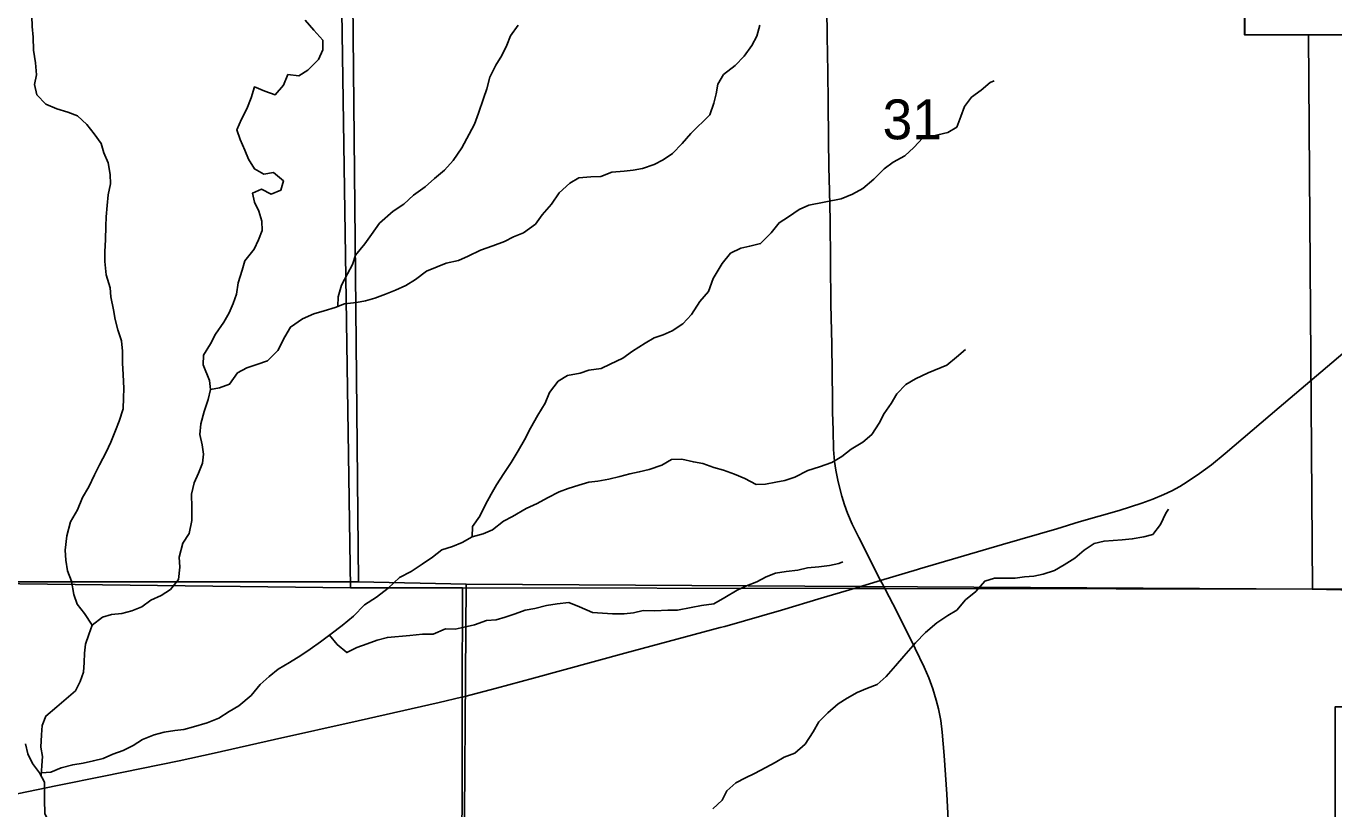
# Model space of a CAD drawing. Extents: x 0 to 34, y 0 to 22.
# Drawn here: x 2.753 to 4.127, y 16.64 to 17.462 of the extents above; entities that cross this region are included whole.
import ezdxf

# ---------------------------------------------------------------- set-up
doc = ezdxf.new("R2010")
doc.units = 0
for name, color, linetype in [('Default', 7, 'Continuous'), ('GM_X_Interstate_Route', 7, 'Continuous'), ('GM_X_Minor_River', 7, 'Continuous'), ('GM_X_Section', 7, 'Continuous'), ('GM_X_Section_Text', 7, 'Continuous'), ('GM_X_State_Route', 7, 'Continuous'), ('GM_X_US_Route', 7, 'Continuous'), ('SH_Text', 7, 'Continuous')]:
    doc.layers.add(name, color=color, linetype=linetype)

msp = doc.modelspace()

# ---------------------------------------------------------------- linework, layer by layer
at = {"layer": 'Default'}
for points in [[(4.0336, 17.4527), (4.0336, 18.2003), (4.0332, 18.2003), (4.0332, 17.4527)], [(4.0336, 18.2003), (5.9872, 18.2003), (5.9872, 17.4527), (4.0336, 17.4527)], [(2.1, 17.8727), (2.1, 16.8795), (2.253, 16.8782), (3.1023, 16.8785), (3.0924, 17.8824)]]:
    msp.add_lwpolyline(points, close=True, dxfattribs=at)
at = {"layer": 'GM_X_Interstate_Route'}
for points in [[(3.0331, 20.9), (2.1, 20.9), (2.1, 16.8784), (2.6014, 16.878), (3.0939, 16.8719), (3.0724, 18.2926), (3.0747, 18.8969), (3.067, 19.3838), (3.0588, 19.9042)], [(2.1, 16.8784), (2.1, 14.1), (3.2011, 14.1), (3.2037, 14.7782), (3.2041, 14.9016), (3.2042, 14.9221), (3.2098, 15.7617), (3.2111, 16.7578), (3.2115, 16.8719), (3.0939, 16.8719), (2.6014, 16.878)]]:
    msp.add_lwpolyline(points, close=True, dxfattribs=at)
for points in [[(3.0724, 18.2926), (3.0939, 16.8719), (3.2115, 16.8719), (3.6203, 16.8714), (3.6554, 16.8713), (4.6269, 16.8701)], [(4.6269, 16.8701), (3.6554, 16.8713), (3.6203, 16.8714), (3.2115, 16.8719), (3.2111, 16.7578), (3.2098, 15.7617), (3.2042, 14.9221), (3.2041, 14.9016), (3.2037, 14.7782), (3.2011, 14.1), (8.2568, 14.1)]]:
    msp.add_lwpolyline(points, dxfattribs=at)
at = {"layer": 'GM_X_Minor_River'}
for points in [[(2.8223, 16.8328), (2.8144, 16.8451), (2.8066, 16.855), (2.8032, 16.8649), (2.8007, 16.879), (2.7966, 16.89), (2.7948, 16.901), (2.7942, 16.9117), (2.7958, 16.9268), (2.7997, 16.9412), (2.807, 16.954), (2.8124, 16.9669), (2.819, 16.9782), (2.8248, 16.9907), (2.8301, 17.0012), (2.8371, 17.0145), (2.8421, 17.025), (2.8471, 17.0371), (2.851, 17.047), (2.8549, 17.0602), (2.8554, 17.0716), (2.8558, 17.0814), (2.8552, 17.0962), (2.8545, 17.108), (2.8543, 17.1205), (2.8532, 17.1316), (2.8495, 17.143), (2.8466, 17.154), (2.8448, 17.1639), (2.8422, 17.1776), (2.8412, 17.1871), (2.8371, 17.2008), (2.8357, 17.2148), (2.8358, 17.2254), (2.8363, 17.2376), (2.8368, 17.252), (2.8373, 17.2615), (2.8381, 17.2736), (2.8394, 17.2846), (2.8417, 17.2963), (2.8414, 17.3062), (2.8393, 17.3184), (2.8348, 17.329), (2.8319, 17.3386), (2.8244, 17.3489), (2.8169, 17.3588), (2.8071, 17.3676), (2.7969, 17.3715), (2.7852, 17.3751), (2.7739, 17.3801), (2.7645, 17.3897), (2.762, 17.4007), (2.7639, 17.4109), (2.7629, 17.4235), (2.7608, 17.4368), (2.7605, 17.4504), (2.7594, 17.4615), (2.7592, 17.4725)], [(2.769, 16.6743), (2.7695, 16.6854), (2.7704, 16.6949), (2.7686, 16.7047), (2.7694, 16.7176), (2.7699, 16.7275), (2.7738, 16.7373), (2.7852, 16.7471), (2.7951, 16.7553), (2.805, 16.764), (2.8097, 16.7738), (2.8132, 16.7836), (2.814, 16.7935), (2.8145, 16.8033), (2.8153, 16.8128), (2.8188, 16.823), (2.8223, 16.8328), (2.8333, 16.8411), (2.8428, 16.844), (2.8538, 16.8451), (2.8641, 16.848), (2.8747, 16.8521), (2.8842, 16.8592), (2.8949, 16.864), (2.9048, 16.8704), (2.9132, 16.8809), (2.9144, 16.8938), (2.9138, 16.9044), (2.9177, 16.9188), (2.9242, 16.929), (2.9273, 16.9426), (2.9271, 16.9563), (2.9268, 16.9703), (2.9296, 16.9824), (2.9342, 16.9923), (2.9385, 17.0029), (2.9393, 17.0123), (2.9379, 17.0222), (2.9357, 17.0332), (2.9365, 17.0442), (2.9401, 17.0571), (2.9443, 17.07), (2.9467, 17.0802), (2.9456, 17.0897), (2.939, 17.1064), (2.9394, 17.1163), (2.9467, 17.1284), (2.9521, 17.1386), (2.9609, 17.151), (2.9663, 17.1608), (2.9705, 17.1706), (2.974, 17.1805), (2.9757, 17.1922), (2.9799, 17.2055), (2.983, 17.2153), (2.9926, 17.2277), (2.9972, 17.2375), (3.0011, 17.2474), (3.0008, 17.2572), (2.9975, 17.2675), (2.993, 17.277), (2.9908, 17.2865), (3.0003, 17.2906), (3.0105, 17.2856), (3.0208, 17.2897), (3.0235, 17.2995), (3.013, 17.3083), (3.0027, 17.3065), (2.993, 17.312), (2.9866, 17.3223), (2.9829, 17.3318), (2.9781, 17.3428), (2.9744, 17.3531), (2.9794, 17.3644), (2.9848, 17.375), (2.9894, 17.3867), (2.9929, 17.3981), (3.0039, 17.3938), (3.0148, 17.3899), (3.0236, 17.4001), (3.0282, 17.411), (3.0396, 17.4098), (3.0491, 17.4158), (3.0602, 17.427), (3.0648, 17.4369), (3.0649, 17.4471), (3.0555, 17.4578), (3.0461, 17.4681)], [(2.9467, 17.0802), (2.9562, 17.082), (2.9668, 17.0861), (2.9752, 17.0977), (2.9851, 17.103), (2.9954, 17.1066), (3.0068, 17.1103), (3.0175, 17.1212), (3.0248, 17.1356), (3.0309, 17.1458), (3.0435, 17.1547), (3.0553, 17.1599), (3.0663, 17.1629), (3.0777, 17.1666), (3.0876, 17.1703), (3.1001, 17.1717), (3.1095, 17.1735), (3.1194, 17.1764), (3.1308, 17.1805), (3.1411, 17.1845), (3.1521, 17.1897), (3.162, 17.1957), (3.1738, 17.2047), (3.1848, 17.2092), (3.1943, 17.2129), (3.2072, 17.2158), (3.2175, 17.2202), (3.2304, 17.2265), (3.2433, 17.2313), (3.2555, 17.2358), (3.265, 17.2406), (3.2756, 17.2447), (3.2882, 17.2541), (3.2951, 17.2639), (3.305, 17.2748), (3.3131, 17.2868), (3.3242, 17.297), (3.3337, 17.3026), (3.3462, 17.3036), (3.3568, 17.3042), (3.3686, 17.3087), (3.3814, 17.3097), (3.3909, 17.3107), (3.4008, 17.3125), (3.4129, 17.3166), (3.4224, 17.3214), (3.4323, 17.3282), (3.4423, 17.3387), (3.4514, 17.3492), (3.4713, 17.3688), (3.4756, 17.3809), (3.4779, 17.3907), (3.4799, 17.4009), (3.4857, 17.4111), (3.4979, 17.4205), (3.5074, 17.4303), (3.5155, 17.4416), (3.5208, 17.4514), (3.524, 17.4631)], [(3.0807, 17.1677), (3.0808, 17.1775), (3.0843, 17.19), (3.0908, 17.2017), (3.0959, 17.2115), (3.099, 17.2214), (3.1089, 17.2334), (3.1158, 17.2432), (3.1242, 17.2549), (3.1387, 17.2677), (3.1498, 17.2748), (3.1601, 17.2845), (3.1723, 17.2931), (3.1822, 17.3018), (3.1925, 17.3108), (3.2017, 17.3209), (3.2109, 17.3341), (3.2186, 17.3485), (3.224, 17.359), (3.2282, 17.3704), (3.2336, 17.3859), (3.2371, 17.3961), (3.2403, 17.4082), (3.2464, 17.421), (3.253, 17.4312), (3.258, 17.4418), (3.2618, 17.4516), (3.2699, 17.4629)], [(3.2218, 16.9257), (3.2219, 16.9363), (3.2296, 16.9473), (3.2357, 16.9597), (3.2415, 16.9703), (3.2472, 16.9801), (3.2549, 16.9922), (3.2626, 17.0035), (3.2699, 17.0159), (3.2768, 17.0276), (3.283, 17.0397), (3.2907, 17.0533), (3.2983, 17.0661), (3.303, 17.0771), (3.3122, 17.0891), (3.3217, 17.0951), (3.335, 17.0976), (3.3444, 17.1006), (3.3573, 17.1024), (3.3668, 17.1068), (3.3801, 17.1131), (3.3901, 17.1206), (3.4034, 17.1289), (3.4129, 17.1345), (3.4224, 17.1378), (3.4319, 17.1419), (3.4429, 17.1493), (3.4521, 17.1591), (3.4609, 17.1727), (3.4701, 17.1832), (3.4748, 17.1968), (3.4844, 17.2127), (3.4932, 17.2236), (3.5038, 17.2288), (3.5133, 17.231), (3.5247, 17.2335), (3.5358, 17.2448), (3.5442, 17.2554), (3.5541, 17.2617), (3.5651, 17.2692), (3.5754, 17.274), (3.6095, 17.2805), (3.6213, 17.2853), (3.6323, 17.2913), (3.6438, 17.3014), (3.6545, 17.312), (3.664, 17.3191), (3.6762, 17.3258), (3.6857, 17.3344), (3.6953, 17.3446), (3.7051, 17.3464), (3.7214, 17.3504), (3.731, 17.356), (3.7352, 17.367), (3.7391, 17.3775), (3.7464, 17.3873), (3.7563, 17.3948), (3.7658, 17.4027), (3.77, 17.4046)], [(2.7692, 16.6777), (2.7789, 16.6784), (2.79, 16.6829), (2.8021, 16.6862), (2.8131, 16.688), (2.8237, 16.6905), (2.834, 16.6927), (2.8442, 16.6972), (2.8552, 16.7012), (2.8655, 16.7064), (2.8754, 16.7128), (2.8876, 16.7176), (2.8982, 16.7205), (2.9092, 16.7223), (2.9187, 16.7234), (2.9289, 16.7259), (2.9433, 16.7304), (2.9555, 16.7352), (2.9665, 16.7423), (2.9764, 16.7482), (2.9894, 16.7591), (2.999, 16.7704), (3.0085, 16.779), (3.018, 16.7865), (3.0298, 16.7936), (3.0416, 16.8011), (3.0515, 16.8078), (3.0622, 16.8153), (3.0736, 16.8236), (3.0851, 16.8326), (3.0969, 16.8423), (3.1087, 16.8543), (3.1213, 16.8622), (3.1335, 16.8716), (3.1453, 16.8828), (3.1575, 16.8892), (3.1693, 16.897), (3.18, 16.9041), (3.1899, 16.912), (3.2009, 16.9153), (3.2111, 16.9198), (3.2218, 16.9257), (3.2332, 16.9286), (3.2431, 16.9331), (3.2545, 16.9421), (3.264, 16.9469), (3.2785, 16.9555), (3.2899, 16.9607), (3.3009, 16.9667), (3.3131, 16.973), (3.3226, 16.9763), (3.3336, 16.98), (3.3442, 16.983), (3.3537, 16.984), (3.3651, 16.9862), (3.3768, 16.9891), (3.3875, 16.9917), (3.3973, 16.9938), (3.4076, 16.9964), (3.4208, 17.0008), (3.4311, 17.0068), (3.4421, 17.0071), (3.4542, 17.0043), (3.464, 17.0027), (3.4757, 16.9984), (3.4856, 16.9956), (3.4973, 16.9913), (3.5082, 16.9867), (3.5199, 16.9805), (3.5297, 16.9808), (3.5407, 16.9829), (3.5502, 16.9848), (3.5608, 16.9884), (3.5742, 16.9951), (3.5867, 16.9992), (3.5996, 17.0036), (3.6099, 17.01), (3.6198, 17.0178), (3.632, 17.0249), (3.6415, 17.0332), (3.6492, 17.0449), (3.6546, 17.0551), (3.6618, 17.0656), (3.668, 17.0758), (3.6772, 17.0856), (3.6874, 17.0916), (3.7007, 17.0979), (3.7205, 17.106), (3.7304, 17.1143), (3.74, 17.1222)], [(3.4746, 16.6398), (3.4845, 16.6492), (3.4891, 16.659), (3.4987, 16.6673), (3.5089, 16.6725), (3.5184, 16.6769), (3.5302, 16.6833), (3.5401, 16.6885), (3.5496, 16.6941), (3.5607, 16.6985), (3.5717, 16.7079), (3.5798, 16.7207), (3.5859, 16.7313), (3.5955, 16.7407), (3.6062, 16.7501), (3.6157, 16.7561), (3.6263, 16.762), (3.637, 16.7665), (3.6472, 16.7706), (3.6568, 16.7788), (3.6663, 16.7901), (3.6751, 16.8003), (3.6874, 16.8142), (3.6981, 16.8251), (3.7099, 16.8352), (3.7213, 16.8431), (3.7308, 16.8487), (3.74, 16.8596), (3.7507, 16.8682), (3.7602, 16.8791), (3.7705, 16.8821), (3.7807, 16.8823), (3.7921, 16.8822), (3.8019, 16.8836), (3.8118, 16.8843), (3.8216, 16.8865), (3.8334, 16.8902), (3.8437, 16.8961), (3.8547, 16.9032), (3.8646, 16.9115), (3.8753, 16.9186), (3.8855, 16.9212), (3.9045, 16.9225), (3.9151, 16.9235), (3.9272, 16.9257), (3.9367, 16.9282), (3.9448, 16.9384), (3.9505, 16.9505), (3.9532, 16.9546)], [(3.0717, 16.8222), (3.08, 16.8125), (3.0901, 16.8041), (3.1004, 16.8093), (3.1114, 16.8133), (3.122, 16.817), (3.1327, 16.82), (3.1562, 16.822), (3.1694, 16.8234), (3.1808, 16.8233), (3.1937, 16.8289), (3.2039, 16.8288), (3.2134, 16.8309), (3.224, 16.8331), (3.2366, 16.8379), (3.2468, 16.8386), (3.2563, 16.8411), (3.2669, 16.8448), (3.2772, 16.8485), (3.2874, 16.8503), (3.2999, 16.8536), (3.3109, 16.8554), (3.3231, 16.8568), (3.3344, 16.8522), (3.348, 16.8463), (3.3692, 16.8446), (3.3813, 16.8449), (3.3911, 16.8459), (3.4014, 16.8481), (3.4135, 16.848), (3.4271, 16.8486), (3.4374, 16.8485), (3.4518, 16.8514), (3.4628, 16.8536), (3.4757, 16.8553), (3.4871, 16.862), (3.5, 16.8695), (3.5099, 16.874), (3.5209, 16.8784), (3.5304, 16.8836), (3.5403, 16.8873), (3.5517, 16.8891), (3.5638, 16.8905), (3.5741, 16.8931), (3.5858, 16.8941), (3.5972, 16.8955), (3.607, 16.8977), (3.6112, 16.8992)], [(2.7523, 16.7083), (2.7549, 16.6977), (2.7597, 16.6874), (2.7672, 16.6778), (2.7724, 16.6679), (2.7723, 16.6493), (2.7729, 16.6349), (2.7777, 16.6242), (2.7818, 16.6109), (2.7843, 16.5999)]]:
    msp.add_lwpolyline(points, dxfattribs=at)
at = {"layer": 'GM_X_Section'}
for points in [[(4.0336, 17.8765), (3.0924, 17.8824), (3.1023, 16.8785), (3.2153, 16.8759), (4.1045, 16.8706), (4.1005, 17.4527), (4.0336, 17.4527)], [(4.1005, 17.4527), (4.1045, 16.8706), (4.2083, 16.8683), (5.1149, 16.8654), (5.0909, 17.4527)], [(3.1023, 16.8785), (3.2153, 16.8759), (3.2082, 15.8593), (3.2075, 15.8525), (2.249, 15.8507), (2.253, 16.8782)], [(4.2148, 16.747), (4.2083, 16.8683), (4.1045, 16.8706), (3.2153, 16.8759), (3.2082, 15.8593), (4.2651, 15.8107), (4.2549, 16), (4.1282, 16), (4.1282, 16.747)]]:
    msp.add_lwpolyline(points, close=True, dxfattribs=at)
at = {"layer": 'GM_X_State_Route'}
for points in [[(3.6004, 17.0565), (3.6001, 17.0694), (3.5995, 17.1277), (3.5985, 17.1701), (3.5979, 17.2582), (3.5971, 17.2886), (3.5965, 17.3143), (3.596, 17.3425), (3.5956, 17.3822), (3.5953, 17.4136), (3.5945, 17.4514), (3.5936, 17.5389)], [(3.6508, 16.8798), (3.6278, 16.925), (3.621, 16.939), (3.6161, 16.9505), (3.6128, 16.9593), (3.6101, 16.9682), (3.6062, 16.9833), (3.6037, 16.9956), (3.6023, 17.0048), (3.6012, 17.0172), (3.6008, 17.0375), (3.6004, 17.0565)], [(3.6556, 16.8707), (3.6549, 16.8721), (3.6535, 16.8748), (3.6508, 16.8798)], [(3.7196, 16.6656), (3.7177, 16.6958), (3.7156, 16.7206), (3.7139, 16.7328), (3.7116, 16.745), (3.7093, 16.754), (3.7057, 16.7658), (3.7014, 16.7774), (3.6965, 16.7888), (3.6871, 16.8083), (3.6677, 16.8473), (3.6556, 16.8707)], [(3.7226, 16.6152), (3.7203, 16.6555), (3.7196, 16.6656)]]:
    msp.add_lwpolyline(points, dxfattribs=at)
at = {"layer": 'GM_X_US_Route'}
msp.add_line((3.6205, 16.8708), (3.6508, 16.8798), dxfattribs=at)
for points in [[(3.6915, 16.8919), (3.779, 16.9176), (3.8358, 16.934), (3.8595, 16.9413), (3.9013, 16.9534), (3.9251, 16.9609), (3.9368, 16.9651), (3.9483, 16.9699), (3.9568, 16.974), (3.965, 16.9784), (3.973, 16.9833), (3.9858, 16.9921), (3.9984, 17.0013), (4.0129, 17.0131), (4.0697, 17.0615), (4.1479, 17.1278)], [(3.6508, 16.8798), (3.6896, 16.8913), (3.6915, 16.8919)], [(3.4821, 16.8303), (3.487, 16.8316), (3.5467, 16.8485), (3.5883, 16.8612), (3.6205, 16.8708)], [(3.2104, 16.7571), (3.2114, 16.7573), (3.2141, 16.7579), (3.2472, 16.7665), (3.2862, 16.777), (3.382, 16.8035), (3.4821, 16.8303)], [(2.7435, 16.6557), (2.7861, 16.6645), (2.8348, 16.6743), (2.914, 16.6904), (2.9505, 16.6983), (3.0141, 16.7127), (3.102, 16.7325), (3.1869, 16.7516), (3.2104, 16.7571)]]:
    msp.add_lwpolyline(points, dxfattribs=at)
at = {"layer": 'SH_Text'}
msp.add_lwpolyline([(4.0336, 18.2003), (5.9868, 18.2003), (5.9868, 17.4527), (4.0336, 17.4527)], close=True, dxfattribs=at)

# ---------------------------------------------------------------- texts
at = {"layer": 'GM_X_Section_Text'}
msp.add_text('31', height=0.04186, rotation=0, dxfattribs=at).set_placement((3.6529, 17.3431))

doc.saveas('drawing.dxf')
